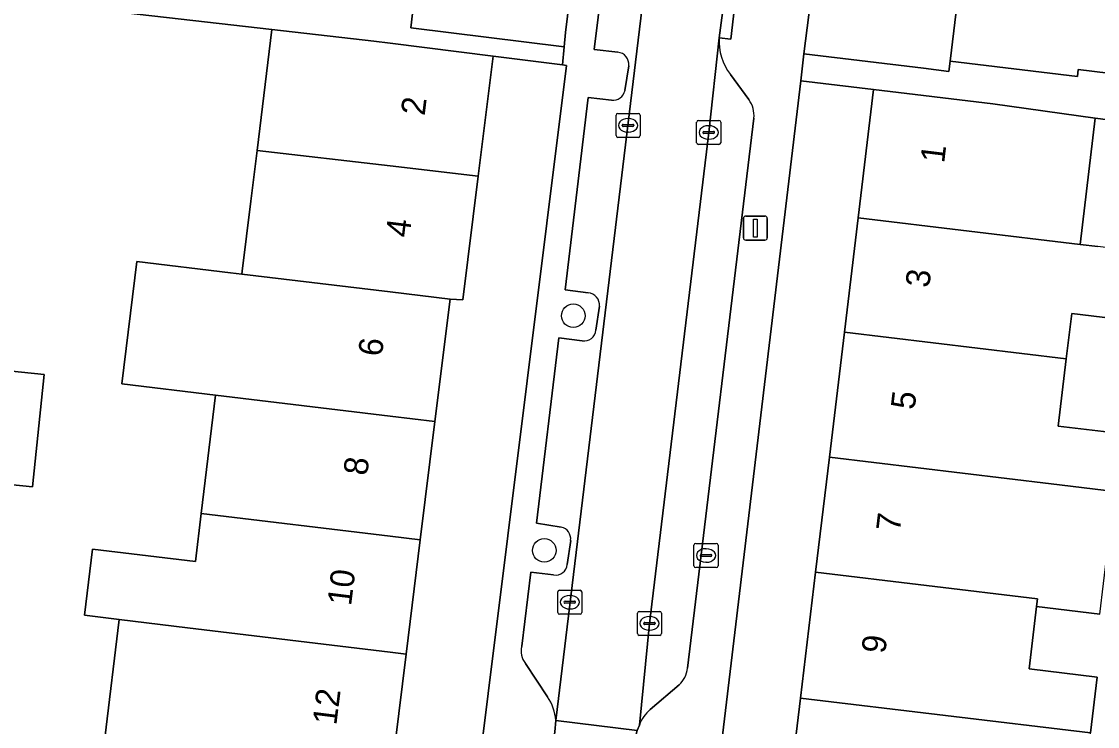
# Model space of a CAD drawing. Extents: x 158086 to 159499, y 382904 to 383981.
# Drawn here: x 158484.67 to 158529.42, y 383321.5 to 383350.79 of the extents above; entities that cross this region are included whole.
import ezdxf

# ---------------------------------------------------------------- set-up
doc = ezdxf.new("R2010")
doc.units = 0
for name, color, linetype in [('IMGEO_Boom', 7, 'Continuous'), ('IMGEO_Brandkraan', 7, 'Continuous'), ('IMGEO_Erf', 7, 'Continuous'), ('IMGEO_Kolk', 7, 'Continuous'), ('IMGEO_Lichtmast', 7, 'Continuous'), ('IMGEO_Pand', 7, 'Continuous'), ('IMGEO_Pand_nummerreeks', 7, 'Continuous'), ('IMGEO_Parkeervlak_open', 7, 'Continuous'), ('IMGEO_Rijbaan_lokaal_open', 7, 'Continuous'), ('IMGEO_Voetpad_open', 7, 'Continuous')]:
    doc.layers.add(name, color=color, linetype=linetype)

msp = doc.modelspace()

# ---------------------------------------------------------------- linework, layer by layer
at = {"layer": 'IMGEO_Boom'}
for centre in [(158507.617, 383338.569), (158506.411, 383328.818)]:
    msp.add_circle(centre, 0.489, dxfattribs=at)
at = {"layer": 'IMGEO_Brandkraan'}
for p, q in [((158512.636, 383328.179), (158512.636, 383329.031)), ((158512.711, 383329.105), (158513.563, 383329.105)), ((158513.124, 383328.885), (158513.149, 383328.885)), ((158513.637, 383329.031), (158513.637, 383328.179)), ((158512.895, 383328.599), (158512.895, 383328.611)), ((158513.333, 383328.562), (158512.935, 383328.562)), ((158512.938, 383328.648), (158513.336, 383328.648)), ((158513.147, 383328.325), (158513.122, 383328.325)), ((158513.379, 383328.611), (158513.379, 383328.599)), ((158513.563, 383328.105), (158512.711, 383328.105))]:
    msp.add_line(p, q, dxfattribs=at)
for points in [[(158512.636, 383328.179), (158512.636, 383329.031)], [(158512.711, 383329.105), (158513.563, 383329.105)], [(158513.637, 383329.031), (158513.637, 383328.179)], [(158513.563, 383328.105), (158512.711, 383328.105)]]:
    msp.add_lwpolyline(points, dxfattribs=at)
for centre, radius, start, end in [((158512.713, 383329.029), 0.0765, 91.552, 178.448), ((158512.713, 383329.029), 0.0765, 91.552, 178.448), ((158513.561, 383329.029), 0.0765, 1.552, 88.448), ((158513.561, 383329.029), 0.0765, 1.552, 88.448), ((158512.935, 383328.608), 0.0403, 85.8775, 175.7526), ((158512.932, 383328.598), 0.0366, 178.938, 274.7102), ((158513.336, 383328.605), 0.043, 264.8664, 352.4533), ((158513.34, 383328.61), 0.0386, 1.7309, 96.639), ((158512.713, 383328.181), 0.0765, 181.552, 268.448), ((158512.713, 383328.181), 0.0765, 181.552, 268.448), ((158513.561, 383328.181), 0.0765, 271.552, 358.448), ((158513.561, 383328.181), 0.0765, 271.552, 358.448)]:
    msp.add_arc(centre, radius, start, end, dxfattribs=at)
for centre, major_axis, ratio, start_param, end_param in [((158513.123, 383328.605), (-0.387, 0.002), 0.722429, 4.712389, 7.853982), ((158513.148, 383328.605), (-0.39, 0.002), 0.717154, 1.570796, 4.712389)]:
    msp.add_ellipse(centre, major_axis=major_axis, ratio=ratio, start_param=start_param, end_param=end_param, dxfattribs=at)
at = {"layer": 'IMGEO_Erf'}
for points in [[(158529.707, 383357.503), (158524.428, 383358.187), (158523.734, 383352.833), (158523.29, 383349.142), (158528.585, 383348.506), (158528.62, 383348.804), (158531.681, 383348.425)], [(158488.132, 383321.013), (158488.727, 383325.948), (158487.288, 383326.121), (158487.62, 383328.868), (158491.905, 383328.351), (158492.147, 383330.352), (158492.742, 383335.268), (158488.847, 383335.738), (158489.46, 383340.827), (158493.357, 383340.357), (158493.838, 383340.299), (158493.852, 383340.414), (158494.208, 383343.334), (158494.465, 383345.441), (158495.077, 383350.462), (158485.705, 383351.537), (158482.088, 383351.952)], [(158544.361, 383344.847), (158529.324, 383346.776), (158528.693, 383341.532), (158529.432, 383341.443)], [(158532.597, 383338.148), (158528.348, 383338.659), (158528.121, 383336.776), (158527.785, 383333.981), (158530.616, 383333.641)], [(158478.863, 383336.823), (158485.617, 383336.121), (158485.133, 383331.454), (158478.379, 383332.156)], [(158529.509, 383326.17), (158526.884, 383326.486), (158526.572, 383323.894), (158529.401, 383323.554), (158529.122, 383321.233)]]:
    msp.add_lwpolyline(points, dxfattribs=at)
for points in [[(158507.33, 383348.969), (158507.162, 383348.995), (158504.282, 383349.355), (158503.662, 383344.369), (158503.023, 383339.223), (158502.491, 383339.255), (158501.862, 383334.168), (158501.254, 383329.253), (158500.667, 383324.506), (158500.058, 383319.575), (158500, 383319.11), (158499.428, 383314.481), (158498.844, 383309.761), (158498.215, 383304.671), (158497.589, 383299.609), (158496.962, 383294.538), (158496.371, 383289.76), (158496.824, 383289.705), (158496.808, 383289.575), (158496.205, 383284.591), (158495.607, 383279.645), (158498.634, 383279.267), (158500, 383290.217)], [(158515.854, 383312.62), (158516.455, 383317.614), (158517.064, 383322.682), (158517.694, 383327.912), (158518.269, 383332.695), (158518.893, 383337.886), (158519.465, 383342.641), (158520.106, 383347.97), (158517.077, 383348.332), (158509.196, 383282.453), (158512.183, 383282.096), (158512.803, 383287.251), (158513.415, 383292.341), (158514.02, 383297.367), (158514.64, 383302.525), (158515.229, 383307.423)]]:
    msp.add_lwpolyline(points, close=True, dxfattribs=at)
at = {"layer": 'IMGEO_Kolk'}
for p, q in [((158509.395, 383346.053), (158509.395, 383346.905)), ((158509.47, 383346.979), (158510.322, 383346.979)), ((158509.883, 383346.759), (158509.908, 383346.759)), ((158510.396, 383346.905), (158510.396, 383346.053)), ((158512.822, 383346.684), (158513.674, 383346.684)), ((158509.654, 383346.473), (158509.654, 383346.485)), ((158510.092, 383346.436), (158509.694, 383346.436)), ((158509.697, 383346.522), (158510.095, 383346.522)), ((158510.138, 383346.485), (158510.138, 383346.473)), ((158512.747, 383345.758), (158512.747, 383346.61)), ((158513.049, 383346.227), (158513.447, 383346.227)), ((158513.235, 383346.464), (158513.26, 383346.464)), ((158513.748, 383346.61), (158513.748, 383345.758)), ((158510.322, 383345.979), (158509.47, 383345.979)), ((158509.906, 383346.199), (158509.881, 383346.199)), ((158513.006, 383346.178), (158513.006, 383346.19)), ((158513.444, 383346.141), (158513.046, 383346.141)), ((158513.258, 383345.904), (158513.233, 383345.904)), ((158513.49, 383346.19), (158513.49, 383346.178)), ((158513.674, 383345.684), (158512.822, 383345.684)), ((158506.971, 383326.239), (158506.971, 383327.091)), ((158507.046, 383327.165), (158507.898, 383327.165)), ((158507.972, 383327.091), (158507.972, 383326.239)), ((158507.23, 383326.659), (158507.23, 383326.671)), ((158507.668, 383326.622), (158507.27, 383326.622)), ((158507.273, 383326.708), (158507.671, 383326.708)), ((158507.459, 383326.945), (158507.484, 383326.945)), ((158507.714, 383326.671), (158507.714, 383326.659)), ((158507.898, 383326.165), (158507.046, 383326.165)), ((158507.482, 383326.385), (158507.457, 383326.385)), ((158510.285, 383325.358), (158510.285, 383326.21)), ((158510.36, 383326.284), (158511.212, 383326.284)), ((158511.286, 383326.21), (158511.286, 383325.358)), ((158510.544, 383325.778), (158510.544, 383325.79)), ((158510.982, 383325.741), (158510.584, 383325.741)), ((158510.587, 383325.827), (158510.985, 383325.827)), ((158510.773, 383326.064), (158510.798, 383326.064)), ((158511.028, 383325.79), (158511.028, 383325.778)), ((158511.212, 383325.284), (158510.36, 383325.284)), ((158510.796, 383325.504), (158510.771, 383325.504))]:
    msp.add_line(p, q, dxfattribs=at)
for points in [[(158509.395, 383346.053), (158509.395, 383346.905)], [(158509.47, 383346.979), (158510.322, 383346.979)], [(158510.396, 383346.905), (158510.396, 383346.053)], [(158512.822, 383346.684), (158513.674, 383346.684)], [(158512.747, 383345.758), (158512.747, 383346.61)], [(158513.748, 383346.61), (158513.748, 383345.758)], [(158510.322, 383345.979), (158509.47, 383345.979)], [(158513.674, 383345.684), (158512.822, 383345.684)], [(158506.971, 383326.239), (158506.971, 383327.091)], [(158507.046, 383327.165), (158507.898, 383327.165)], [(158507.972, 383327.091), (158507.972, 383326.239)], [(158507.898, 383326.165), (158507.046, 383326.165)], [(158510.285, 383325.358), (158510.285, 383326.21)], [(158510.36, 383326.284), (158511.212, 383326.284)], [(158511.286, 383326.21), (158511.286, 383325.358)], [(158511.212, 383325.284), (158510.36, 383325.284)]]:
    msp.add_lwpolyline(points, dxfattribs=at)
for centre, radius, start, end in [((158509.472, 383346.903), 0.0765, 91.552, 178.448), ((158509.472, 383346.903), 0.0765, 91.552, 178.448), ((158510.32, 383346.903), 0.0765, 1.552, 88.448), ((158510.32, 383346.903), 0.0765, 1.552, 88.448), ((158512.824, 383346.608), 0.0765, 91.552, 178.448), ((158512.824, 383346.608), 0.0765, 91.552, 178.448), ((158513.672, 383346.608), 0.0765, 1.552, 88.448), ((158513.672, 383346.608), 0.0765, 1.552, 88.448), ((158509.694, 383346.482), 0.0403, 85.8775, 175.7526), ((158509.691, 383346.472), 0.0366, 178.938, 274.7102), ((158510.095, 383346.479), 0.043, 264.8664, 352.4533), ((158510.099, 383346.484), 0.0386, 1.7309, 96.639), ((158513.046, 383346.187), 0.0403, 85.8775, 175.7526), ((158513.451, 383346.189), 0.0386, 1.7309, 96.639), ((158509.472, 383346.055), 0.0765, 181.552, 268.448), ((158509.472, 383346.055), 0.0765, 181.552, 268.448), ((158510.32, 383346.055), 0.0765, 271.552, 358.448), ((158510.32, 383346.055), 0.0765, 271.552, 358.448), ((158513.043, 383346.177), 0.0366, 178.938, 274.7102), ((158513.447, 383346.184), 0.043, 264.8664, 352.4533), ((158512.824, 383345.76), 0.0765, 181.552, 268.448), ((158512.824, 383345.76), 0.0765, 181.552, 268.448), ((158513.672, 383345.76), 0.0765, 271.552, 358.448), ((158513.672, 383345.76), 0.0765, 271.552, 358.448), ((158507.048, 383327.089), 0.0765, 91.552, 178.448), ((158507.048, 383327.089), 0.0765, 91.552, 178.448), ((158507.896, 383327.089), 0.0765, 1.552, 88.448), ((158507.896, 383327.089), 0.0765, 1.552, 88.448), ((158507.27, 383326.668), 0.0403, 85.8775, 175.7526), ((158507.267, 383326.658), 0.0366, 178.938, 274.7102), ((158507.671, 383326.665), 0.043, 264.8664, 352.4533), ((158507.675, 383326.67), 0.0386, 1.7309, 96.639), ((158507.048, 383326.241), 0.0765, 181.552, 268.448), ((158507.048, 383326.241), 0.0765, 181.552, 268.448), ((158507.896, 383326.241), 0.0765, 271.552, 358.448), ((158507.896, 383326.241), 0.0765, 271.552, 358.448), ((158510.362, 383326.208), 0.0765, 91.552, 178.448), ((158510.362, 383326.208), 0.0765, 91.552, 178.448), ((158511.21, 383326.208), 0.0765, 1.552, 88.448), ((158511.21, 383326.208), 0.0765, 1.552, 88.448), ((158510.584, 383325.787), 0.0403, 85.8775, 175.7526), ((158510.581, 383325.777), 0.0366, 178.938, 274.7102), ((158510.985, 383325.784), 0.043, 264.8664, 352.4533), ((158510.989, 383325.789), 0.0386, 1.7309, 96.639), ((158510.362, 383325.36), 0.0765, 181.552, 268.448), ((158510.362, 383325.36), 0.0765, 181.552, 268.448), ((158511.21, 383325.36), 0.0765, 271.552, 358.448), ((158511.21, 383325.36), 0.0765, 271.552, 358.448)]:
    msp.add_arc(centre, radius, start, end, dxfattribs=at)
for centre, major_axis, ratio, start_param, end_param in [((158509.882, 383346.479), (-0.387, 0.002), 0.722429, 4.712389, 7.853982), ((158509.907, 383346.479), (-0.39, 0.002), 0.717154, 1.570796, 4.712389), ((158513.234, 383346.184), (-0.387, 0.002), 0.722429, 4.712389, 7.853982), ((158513.259, 383346.184), (-0.39, 0.002), 0.717154, 1.570796, 4.712389), ((158507.458, 383326.665), (-0.387, 0.002), 0.722429, 4.712389, 7.853982), ((158507.483, 383326.665), (-0.39, 0.002), 0.717154, 1.570796, 4.712389), ((158510.772, 383325.784), (-0.387, 0.002), 0.722429, 4.712389, 7.853982), ((158510.797, 383325.784), (-0.39, 0.002), 0.717154, 1.570796, 4.712389)]:
    msp.add_ellipse(centre, major_axis=major_axis, ratio=ratio, start_param=start_param, end_param=end_param, dxfattribs=at)
at = {"layer": 'IMGEO_Lichtmast'}
for p, q in [((158514.791, 383342.71), (158515.581, 383342.71)), ((158515.581, 383342.71), (158514.791, 383342.71)), ((158514.691, 383341.81), (158514.691, 383342.61)), ((158514.691, 383342.61), (158514.691, 383341.81)), ((158515.681, 383342.61), (158515.681, 383341.81)), ((158515.681, 383341.81), (158515.681, 383342.61)), ((158515.581, 383341.71), (158514.791, 383341.71)), ((158514.791, 383341.71), (158515.581, 383341.71))]:
    msp.add_line(p, q, dxfattribs=at)
msp.add_lwpolyline([(158515.111, 383342.585), (158515.261, 383342.585), (158515.261, 383341.835), (158515.111, 383341.835), (158515.111, 383342.585)], dxfattribs=at)
for centre, start, end in [((158514.791, 383342.61), 90, 180), ((158514.791, 383342.61), 90, 180), ((158515.581, 383342.61), 0, 90), ((158515.581, 383342.61), 360, 90), ((158514.791, 383341.81), 180, 270), ((158514.791, 383341.81), 180, 270), ((158515.581, 383341.81), 270, 0), ((158515.581, 383341.81), 270, 0)]:
    msp.add_arc(centre, 0.1, start, end, dxfattribs=at)
at = {"layer": 'IMGEO_Pand'}
for points in [[(158509.577, 383368.866), (158509.21, 383368.911), (158508.497, 383369.862), (158508.542, 383370.23), (158503.549, 383370.846), (158503.351, 383370.87), (158503.327, 383370.676), (158502.263, 383361.935), (158501.745, 383357.675), (158500.936, 383351.127), (158500.862, 383350.529), (158507.233, 383349.742), (158507.29, 383350.336), (158508.172, 383357.482), (158508.689, 383361.668)], [(158525.457, 383368.377), (158525.15, 383368.417), (158519.734, 383369.12), (158517.21, 383349.447), (158522.175, 383348.851), (158523.24, 383348.723), (158523.29, 383349.142), (158523.734, 383352.833), (158524.428, 383358.187), (158524.154, 383358.223)], [(158503.662, 383344.369), (158504.282, 383349.355), (158500, 383349.89), (158499.321, 383349.975), (158495.077, 383350.462), (158494.465, 383345.441), (158500, 383344.796)], [(158528.693, 383341.532), (158529.324, 383346.776), (158525.071, 383347.373), (158520.106, 383347.97), (158519.465, 383342.641)], [(158503.662, 383344.369), (158500, 383344.796), (158494.465, 383345.441), (158494.208, 383343.334), (158493.852, 383340.414), (158493.838, 383340.299), (158500, 383339.556), (158502.491, 383339.255), (158503.023, 383339.223)], [(158532.942, 383341.021), (158532.031, 383341.131), (158529.432, 383341.443), (158528.693, 383341.532), (158519.465, 383342.641), (158518.893, 383337.886), (158528.121, 383336.776), (158528.348, 383338.659), (158532.597, 383338.148)], [(158502.491, 383339.255), (158500, 383339.556), (158493.838, 383340.299), (158493.357, 383340.357), (158489.46, 383340.827), (158488.847, 383335.738), (158492.742, 383335.268), (158500, 383334.393), (158501.862, 383334.168)], [(158528.121, 383336.776), (158518.893, 383337.886), (158518.269, 383332.695), (158527.497, 383331.586), (158530.123, 383331.271), (158530.328, 383331.246), (158530.616, 383333.641), (158527.785, 383333.981)], [(158478.379, 383332.156), (158485.133, 383331.454), (158485.617, 383336.121), (158478.863, 383336.823)], [(158492.742, 383335.268), (158492.147, 383330.352), (158500, 383329.404), (158501.254, 383329.253), (158501.862, 383334.168), (158500, 383334.393)], [(158530.123, 383331.271), (158527.497, 383331.586), (158518.269, 383332.695), (158517.694, 383327.912), (158526.922, 383326.802), (158526.884, 383326.486), (158529.509, 383326.17)], [(158488.727, 383325.948), (158491.573, 383325.604), (158500, 383324.587), (158500.667, 383324.506), (158501.254, 383329.253), (158500, 383329.404), (158492.147, 383330.352), (158491.905, 383328.351), (158487.62, 383328.868), (158487.288, 383326.121)], [(158526.884, 383326.486), (158526.922, 383326.802), (158517.694, 383327.912), (158517.064, 383322.682), (158529.122, 383321.233), (158529.401, 383323.554), (158526.572, 383323.894)], [(158488.727, 383325.948), (158488.132, 383321.013), (158500.058, 383319.575), (158500.667, 383324.506), (158500, 383324.587), (158491.573, 383325.604)], [(158525.684, 383316.504), (158528.513, 383316.164), (158529.122, 383321.233), (158517.064, 383322.682), (158516.455, 383317.614)]]:
    msp.add_lwpolyline(points, close=True, dxfattribs=at)
at = {"layer": 'IMGEO_Parkeervlak_open'}
for points in [[(158506.884, 383321.754), (158511.891, 383363.082), (158513.087, 383371.78)], [(158510.764, 383360.158), (158509.802, 383360.29), (158508.481, 383349.634), (158509.471, 383349.521)], [(158513.687, 383350.119), (158513.247, 383346.183), (158510.785, 383325.784), (158510.364, 383321.557)], [(158509.922, 383348.959), (158509.767, 383347.933)], [(158514.919, 383347.548), (158514.154, 383348.598)], [(158509.203, 383347.527), (158508.242, 383347.638), (158507.284, 383339.645), (158508.238, 383339.516)], [(158512.369, 383323.918), (158515.129, 383346.779)], [(158508.702, 383338.967), (158508.557, 383337.971)], [(158507.989, 383337.525), (158507.019, 383337.656), (158506.088, 383329.951), (158507.119, 383329.788)], [(158507.508, 383329.235), (158507.368, 383328.232)], [(158506.8, 383327.802), (158505.854, 383327.913), (158505.472, 383324.839)], [(158505.623, 383324.12), (158506.539, 383322.729)], [(158510.815, 383322.204), (158512.013, 383323.225)]]:
    msp.add_lwpolyline(points, dxfattribs=at)
for centre, radius, start, end in [((158515.823, 383349.943), 2.143, 175.2805, 218.8561), ((158509.417, 383349.015), 0.508, 353.6232, 83.8702), ((158509.267, 383348.033), 0.51, 262.7617, 348.7354), ((158514.019, 383346.889), 1.116, 354.3416, 36.2064), ((158508.209, 383339.021), 0.496, 353.7205, 86.6866), ((158508.059, 383338.021), 0.501, 261.9877, 354.2911), ((158506.995, 383329.288), 0.515, 354.1322, 76.1156), ((158506.887, 383328.277), 0.483, 259.5546, 354.6999), ((158506.261, 383324.629), 0.817, 165.1319, 218.5892), ((158511.204, 383324.078), 1.176, 313.4584, 352.1617), ((158505.087, 383321.667), 1.799, 2.7839, 36.1884), ((158511.821, 383321.022), 1.553, 130.4071, 159.835)]:
    msp.add_arc(centre, radius, start, end, dxfattribs=at)
at = {"layer": 'IMGEO_Rijbaan_lokaal_open'}
msp.add_lwpolyline([(158513.235, 383373.724), (158513.22, 383373.391), (158513.205, 383373.07), (158513.087, 383371.78), (158511.891, 383363.082), (158506.884, 383321.754), (158510.271, 383321.33), (158510.364, 383321.557), (158510.785, 383325.784), (158513.247, 383346.183), (158513.687, 383350.119), (158514.179, 383353.86), (158514.207, 383354.088), (158515.248, 383362.604), (158516.412, 383371.549), (158516.618, 383372.578)], dxfattribs=at)
msp.add_lwpolyline([(158509.706, 383316.881), (158509.74, 383317.163), (158509.769, 383317.504), (158510.178, 383320.725), (158510.198, 383321.037), (158510.235, 383321.186), (158510.271, 383321.33), (158506.884, 383321.754), (158506.855, 383321.275), (158506.425, 383317.943), (158506.35, 383317.307)], close=True, dxfattribs=at)
at = {"layer": 'IMGEO_Voetpad_open'}
for points in [[(158508.652, 383277.913), (158509.061, 383281.327), (158509.196, 383282.453), (158517.077, 383348.332), (158517.21, 383349.447), (158519.734, 383369.12), (158520.1, 383372.893), (158516.792, 383373.293)], [(158511.394, 383369.843), (158508.542, 383370.23), (158508.497, 383369.862), (158509.21, 383368.911), (158509.577, 383368.866), (158508.689, 383361.668), (158508.172, 383357.482), (158507.29, 383350.336), (158507.233, 383349.742), (158507.162, 383348.995), (158507.33, 383348.969), (158500, 383290.217), (158498.634, 383279.267), (158498.484, 383278.066), (158498.201, 383275.747), (158497.468, 383270.066), (158496.369, 383261.093), (158495.88, 383257.124), (158498.978, 383256.786), (158499.061, 383257.447), (158499.527, 383261.181)], [(158509.471, 383349.521), (158508.481, 383349.634), (158509.802, 383360.29), (158510.764, 383360.158)], [(158482.088, 383351.952), (158485.705, 383351.537), (158495.077, 383350.462), (158499.321, 383349.975), (158500, 383349.89), (158504.282, 383349.355), (158507.162, 383348.995), (158507.233, 383349.742), (158500.862, 383350.529), (158500.936, 383351.127), (158497.44, 383351.563), (158497.396, 383351.231), (158495.038, 383351.543), (158489.293, 383352.304), (158485.348, 383352.827), (158485.376, 383353.038), (158477.499, 383354.002)], [(158514.207, 383354.088), (158514.179, 383353.86), (158514.603, 383353.783), (158514.162, 383350.058), (158513.687, 383350.119)], [(158531.681, 383348.425), (158528.62, 383348.804), (158528.585, 383348.506), (158523.29, 383349.142), (158523.24, 383348.723), (158522.175, 383348.851), (158517.21, 383349.447), (158517.077, 383348.332), (158520.106, 383347.97), (158525.071, 383347.373), (158529.324, 383346.776), (158544.361, 383344.847)], [(158509.767, 383347.933), (158509.922, 383348.959)], [(158514.154, 383348.598), (158514.919, 383347.548)], [(158508.238, 383339.516), (158507.284, 383339.645), (158508.242, 383347.638), (158509.203, 383347.527)], [(158515.129, 383346.779), (158512.369, 383323.918)], [(158508.557, 383337.971), (158508.702, 383338.967)], [(158507.119, 383329.788), (158506.088, 383329.951), (158507.019, 383337.656), (158507.989, 383337.525)], [(158507.368, 383328.232), (158507.508, 383329.235)], [(158505.472, 383324.839), (158505.854, 383327.913), (158506.8, 383327.802)], [(158506.539, 383322.729), (158505.623, 383324.12)], [(158512.013, 383323.225), (158510.815, 383322.204)], [(158506.35, 383317.307), (158506.425, 383317.943), (158506.855, 383321.275), (158506.884, 383321.754)], [(158510.364, 383321.557), (158510.271, 383321.33), (158510.235, 383321.186), (158510.198, 383321.037), (158510.178, 383320.725), (158509.769, 383317.504), (158509.74, 383317.163), (158509.706, 383316.881), (158509.745, 383316.595), (158510.058, 383315.885), (158510.974, 383314.549)]]:
    msp.add_lwpolyline(points, dxfattribs=at)
msp.add_lwpolyline([(158513.687, 383350.119), (158514.162, 383350.058), (158514.603, 383353.783), (158514.179, 383353.86)], close=True, dxfattribs=at)
for centre, radius, start, end in [((158515.823, 383349.943), 2.143, 175.2805, 218.8561), ((158509.417, 383349.015), 0.508, 353.6232, 83.8702), ((158509.267, 383348.033), 0.51, 262.7617, 348.7354), ((158514.019, 383346.889), 1.116, 354.3416, 36.2064), ((158508.209, 383339.021), 0.496, 353.7205, 86.6866), ((158508.059, 383338.021), 0.501, 261.9877, 354.2911), ((158506.995, 383329.288), 0.515, 354.1322, 76.1156), ((158506.887, 383328.277), 0.483, 259.5546, 354.6999), ((158506.261, 383324.629), 0.817, 165.1319, 218.5892), ((158511.204, 383324.078), 1.176, 313.4584, 352.1617), ((158505.087, 383321.667), 1.799, 2.7839, 36.1884), ((158511.821, 383321.022), 1.553, 130.4071, 159.835)]:
    msp.add_arc(centre, radius, start, end, dxfattribs=at)

# ---------------------------------------------------------------- texts
at = {"layer": 'IMGEO_Pand_nummerreeks'}
for s, rotation, p in [('2', 82.9167, (158501.432, 383346.858)), ('1', 83.1417, (158523.039, 383344.885)), ('4', 82.9185, (158500.803, 383341.794)), ('3', 83.1419, (158522.416, 383339.704)), ('6', 82.9528, (158499.654, 383336.848)), ('5', 83.1419, (158521.807, 383334.637)), ('8', 82.9515, (158499.042, 383331.9)), ('7', 83.1419, (158521.197, 383329.569)), ('10', 82.9515, (158498.374, 383326.489)), ('9', 83.1419, (158520.588, 383324.502)), ('12', 82.9515, (158497.761, 383321.53))]:
    msp.add_text(s, height=1, rotation=rotation, dxfattribs=at).set_placement(p)

doc.saveas('drawing.dxf')
